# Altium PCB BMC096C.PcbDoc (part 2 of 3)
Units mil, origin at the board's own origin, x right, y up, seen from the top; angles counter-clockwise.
Board outline 5500 x 3200 mil, 4 copper layers (Top Layer, Signal Layer 1, Signal Layer 2, Bottom Layer), stack 61.6 mil thick; 174 components, 74 nets, 402 pads, 1110 vias.
Unrouted connection lines stored in the file: 741.
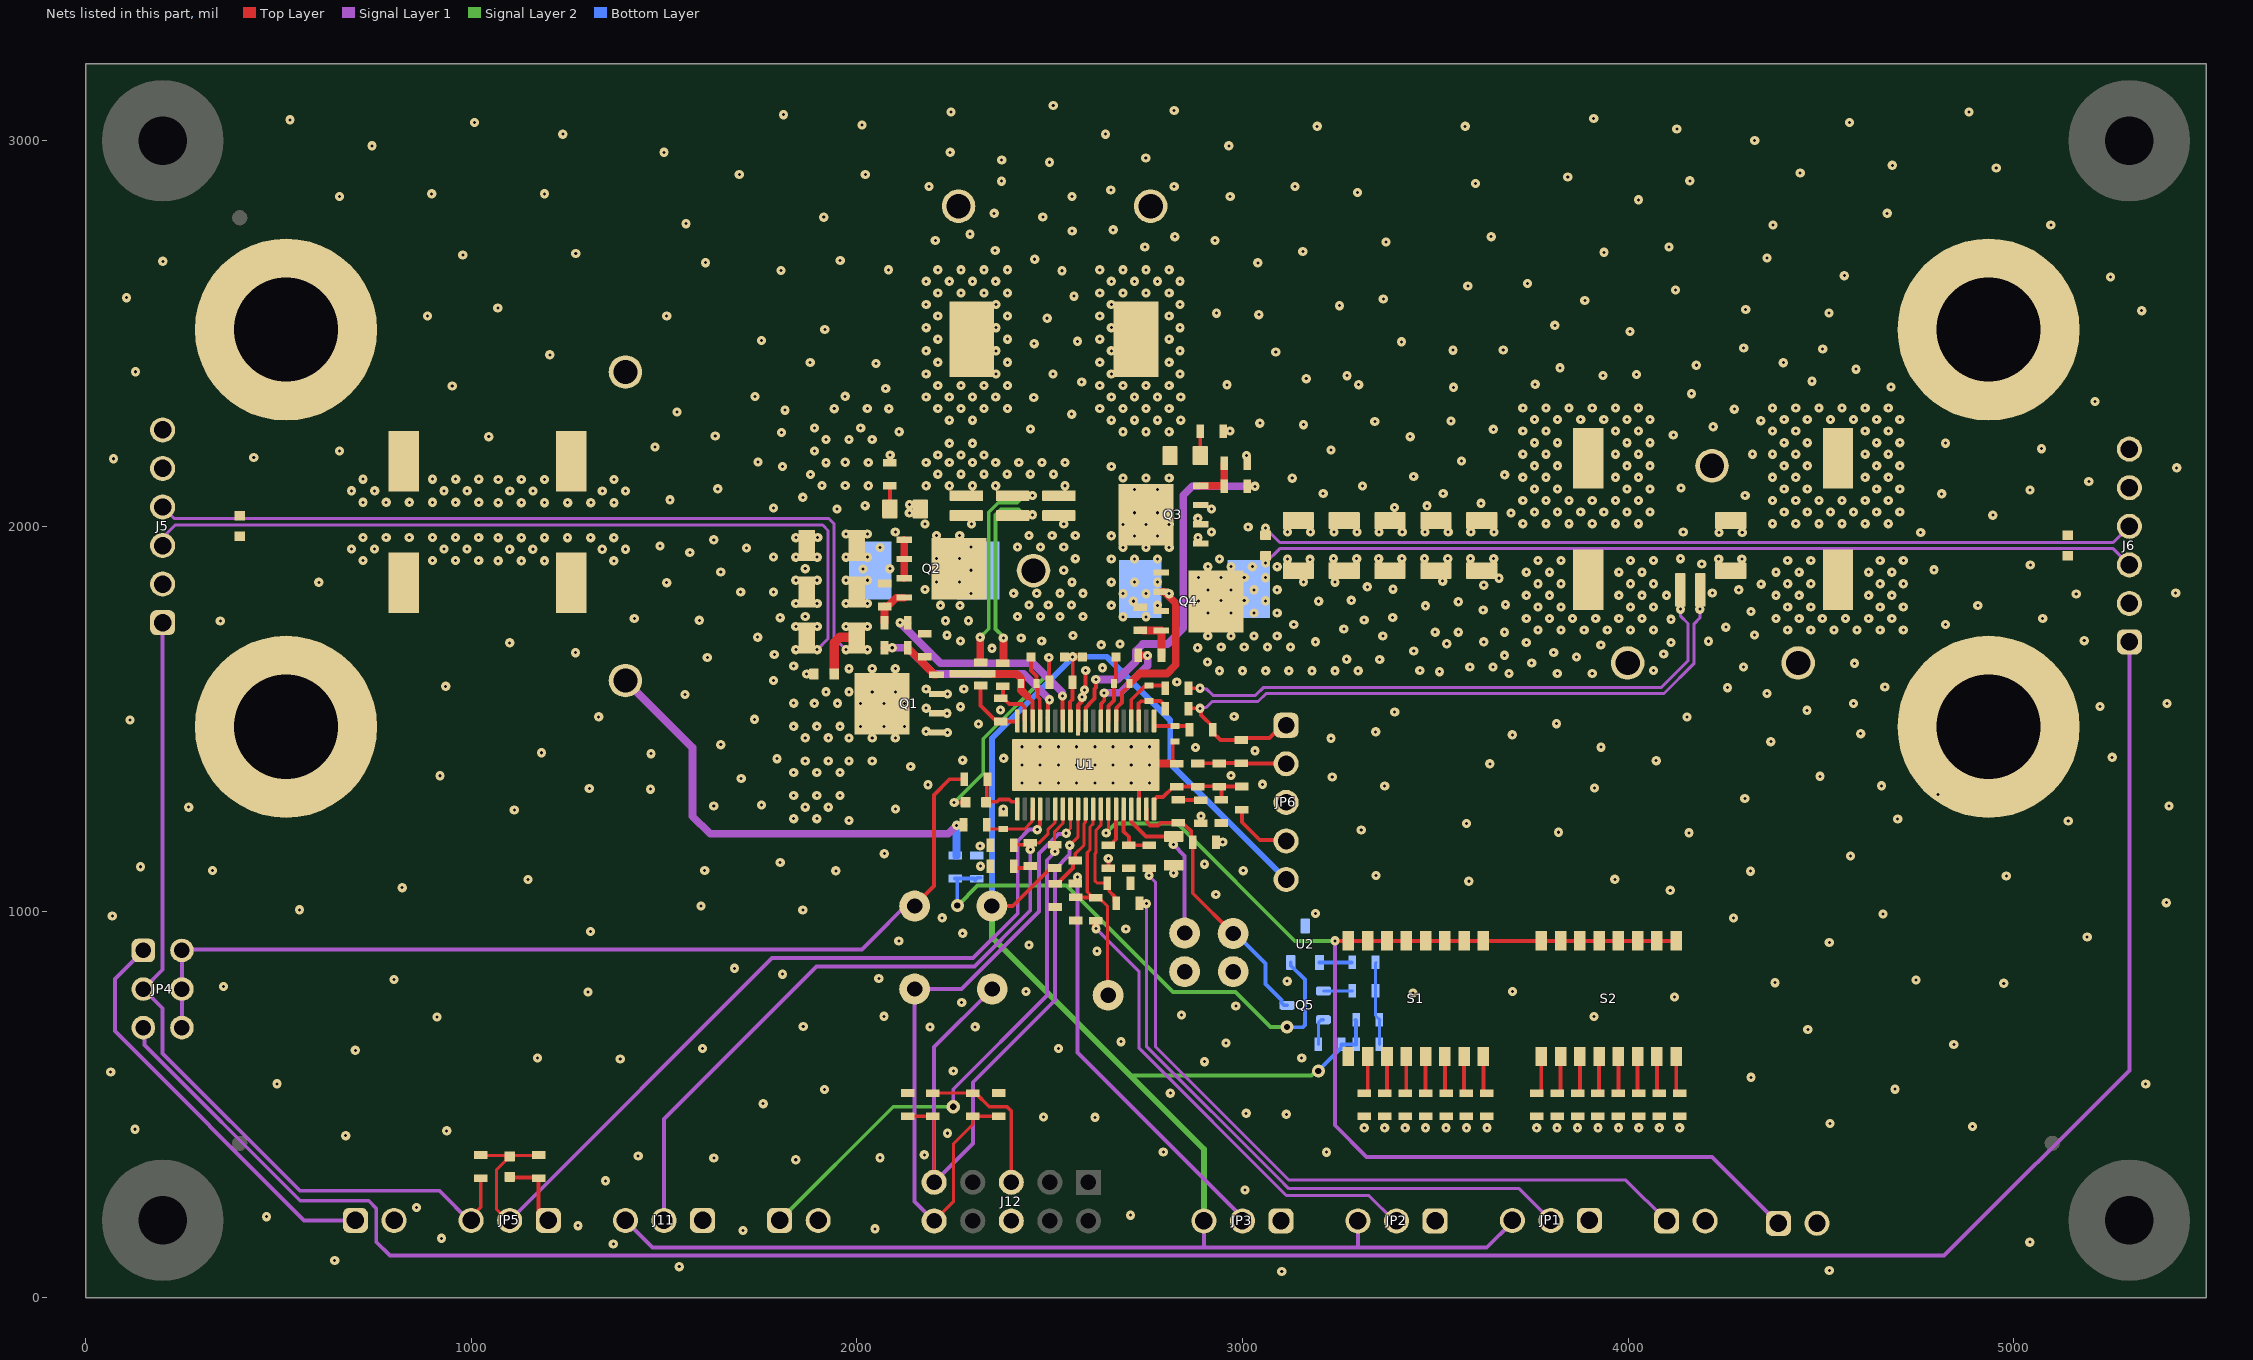
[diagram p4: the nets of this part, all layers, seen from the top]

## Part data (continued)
S1 S2: library part CMP-0002229-1, "Switch, SPST, 8 Pos, 25mA, 24VDC, SMD", CurrentRating_mA=25A, Manufacturer="CTS Electrocomponents", Supplier Part Number 1=CT2188LPST-ND
SH-JP1 SH-JP2 SH-JP3 SH-JP4 SH-JP5: library part CMP-0078738-1, "Single Operation 2.54mm Pitch Open Top Jumper Socket", Manufacturer=Harwin, Supplier Part Number 1=952-2881-ND
TP1: library part CMP-0055147-2, "Test Point, Multipurpose, Red, TH", Color=Red, Manufacturer="Keystone Electronics", Supplier Part Number 1=36-5010-ND
TP2 TP8: library part CMP-0055150-2, "Test Point, Multipurpose, Orange, TH", Color=Orange, Manufacturer="Keystone Electronics", Supplier Part Number 1=36-5013-ND
TP3 TP4: library part CMP-0055148-2, "Test Point, Multipurpose, Black, TH", Color=Black, Manufacturer="Keystone Electronics", Supplier Part Number 1=36-5011-ND
TP5 TP6: library part CMP-0055149-2, "Test Point, Multipurpose, White, TH", Color=White, Manufacturer="Keystone Electronics", Supplier Part Number 1=36-5012-ND
TP7: library part CMP-0055159-2, "Test Point, Multipurpose, Grey, TH", Color=Grey, Manufacturer="Keystone Electronics", Supplier Part Number 1=36-5128-ND
TP9 TP10 TP11 TP12 TP13 TP14 TP15: library part CMP-0055141-2, "Test Point, Miniature, Yellow, TH", Color=Yellow, Manufacturer="Keystone Electronics", Supplier Part Number 1=36-5004-ND
TP16 TP17: library part CMP-0055138-2, "Test Point, Miniature, Black, TH", Color=Black, Manufacturer="Keystone Electronics", Supplier Part Number 1=36-5001-ND
U1: library part CMP-0094661-2, "Wide VIN Bidirectional 4 Switch Buck-Boost Controller", Manufacturer="Texas Instruments", Max Supply Voltage=78V, Min Supply Voltage=2.8V, Nominal Supply Current=25uA, Operating Temperature Range="-40°C to +125°C", Output Voltage=3.3-78V, Switching Frequency=100-2000kHz
U2: library part CMP-0032992-1, "Low-Voltage Adjustable Precision Shunt Regulator, 129 ppm / degC, 80 mA, 0 to 70 degC, 3-pin SOT-23 (DBZ), Green (RoHS & no Sb/Br)", Manufacturer="Texas Instruments", Rating=Catalog, Temp Coeff(Max)(ppm/ degree C)=129
ZZ2: library part CMP-0077236-1
ZZ3: library part CMP-0077237-1
ZZ4: library part CMP-0077238-1

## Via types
v1: diameter 24, hole 7.87, Top Layer to Bottom Layer, tented both sides, 1082 vias
v2: diameter 19.68, hole 7.87, Top Layer to Bottom Layer, 24 vias
v3: diameter 34, hole 16, Top Layer to Bottom Layer, tented both sides, 4 vias

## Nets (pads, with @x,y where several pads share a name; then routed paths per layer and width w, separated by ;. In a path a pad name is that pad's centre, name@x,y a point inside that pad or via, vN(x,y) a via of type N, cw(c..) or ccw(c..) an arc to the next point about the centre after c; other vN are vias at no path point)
AGND: C18.2 C19.2 C20.1 C26.1 C27.2 C28.2 C33.1 C34.2 C35.2 C36.2 C37.2 J7.2 J8.2 J9.2 J10.2 J11.1 J12.6 JP1.1 JP2.1 JP3.1 JP5.1 JP6.3 NT1.2 R2.1 R15.1 R18.1 R20.1 R21.1 R24.1 R25.1 R26.1 R27.1 R28.1 R29.1 R30.1 R31.1 R32.1 R33.1 R34.1 R35.1 R36.1 R37.1 R38.1 R51.1 R52.1 R54.1 S1.1 TP16.1 TP17.1 U1.17 U1.39 U2.3 | length 504.7
  Top Layer w10: C28.2@1100,312.92 1101.71,311.21 1173.29,311.21 R15.1@1175,309.5 1175,225.49 1200,200.49 JP5.1@1200,194.41 ; C26.1@2380,1255 v1(2380,1267) ; U1.39@2574,1432.24 v2(2570,1428.24) 2593.62,1404.62 U1.39@2593.62,1381 ; R20.1@2652,1113 2652.42,1113.42 v1(2652.42,1138.44) ; U1.39@2711,1333 2717.49,1333 2731.42,1319.07 U1.17@2731.42,1266.83 ; v2(2758.98,1428.24) U1.39@2760.36,1429.63 ; C27.2@2819.22,1442 2819.22,1386.78 R2.1@2820,1386
  Top Layer w20: U1.39@2759,1383 2761,1385 R2.1@2824,1385
  other v1: 3102.03,67.61 4522.07,70.11 1539.59,80 646.16,96.1 1368.62,138.97 5042.03,143.61 922.99,153.64 1704.82,173.95 2047.48,178.16 1277.24,186.36 469.03,209.61 2710.03,213.43 858.03,233.61 3006.74,278.87 1348.32,302.56 1841.75,357.28 1629.17,362.08 2060.46,362.47 1433.18,366.86 2175.13,370.21 2795.01,377.44 3218.03,377.05 674.65,419.78 2235,426 936.53,432.3 128.58,436.43 3316,440 3369,440 3422,440 3475,440 3528,440 3581,440 3634,440 3763,440 3816,440 3869,440 3922,440 3975,440 4028,440 4081,440 4134,440 4893.06,443.58 4523.75,451.53 2617.52,467.27 2484.4,468.4 3113.92,475.17 3009.86,477.65 1757.39,502.65 2813,530 1916.52,539.73 4692.23,540.42 496.54,554.14 5342.25,553.84 4318.82,571.14 65.22,584.61 2250.33,587.61 2901.82,611.68 1386.67,618.45 1172.1,620.87 3153.64,621 699.61,641.01 1600,645.57 2523.35,645.57 4844.8,656.15 2957.56,660.24 2685.21,663.58 4466.2,694.96 2190.13,701.7 2307.16,702.1 1861.22,702.54 911.17,727.19 2070.85,729.14 3911.54,729.01 2842.03,732.4 2983.05,756.09 2271.94,764.79 4120.45,779.64 3442.22,789.93 1303.19,792.19 2438.67,793.42 3700.61,793.75 357.77,806.86 4974.29,814.75 4381.03,816.61 3116.18,820.39 4747.03,823.61 800,824.87 2057.03,827.61 1807.34,838.51 1683.03,853.61 2623.16,898.24 2446.76,914.12 4521.89,920.8 2108.95,924.26 5190.55,934.87 2274.51,944.55 1309.7,948.98 2697.62,955.78 4273.26,984.26 2221.52,984.54 69.5,989.45 4661.34,994.85 3189.74,995.55 554.7,1005.43 1860,1004.63 1596.23,1015.45 5396,1024 2931.15,1044.9 4109.45,1055.99 821.05,1062.72 3587.09,1079.53 1147.19,1083.99 3965.7,1084.39 4981,1093 3346.33,1094.54 2821.83,1100.37 1945.74,1106.45 4317.87,1105.61 3002.23,1106.95 329.47,1107.62 1605.68,1107.62 142.76,1117.08 2321,1118.57 2901.82,1123.67 1801.34,1128.01 4577,1145 2071.36,1151.13 2320,1170.68 2949,1181.04 4158.2,1205.15 3819.87,1206.61 3308.18,1212.16 3581,1229 1980,1236.89 2892.5,1248.92 2100.12,1266.61 4302.99,1293.92 3913,1321.57 3369,1326.35 2184.71,1329.78 3052.03,1330.83 3232.99,1350.09 2970.33,1353.69 2139.8,1377.05 3641.54,1384.08 4073.07,1392.14 2274.51,1393.59 2380.87,1398.32 3032.77,1417.68 2878.05,1426.17 3929.74,1427.07 3229.76,1450.09 3699.82,1459.08 3345.73,1466.88 2315.62,1487.13 3814.78,1488.19 4153.11,1505.65 2978.71,1507 3394.81,1518.29
  other v2: 2428.27,1333.76 2475.51,1333.76 2522.76,1333.76 2570,1333.76 2617.24,1333.76 2664.49,1333.76 2711.73,1333.76 2758.98,1333.76 2428.27,1381 2475.51,1381 2522.76,1381 2570,1381 2617.24,1381 2664.49,1381 2711.73,1381 2758.98,1381 2428.27,1428.24 2475.51,1428.24 2522.76,1428.24 2617.24,1428.24 2664.49,1428.24 2711.73,1428.24
BIAS: C29.2 R44.1 U1.1 | length 164.4
  Top Layer w10: C29.2@2335.53,1284.59 C29.2@2336.43,1285.5 ; R44.1@2338.78,1344.16 2337.15,1342.54 2337.15,1286.22 C29.2@2336.43,1285.5 ; U1.1@2416.46,1266.83 2416.46,1284.59 2415.55,1285.5 2401.41,1285.5 2395.03,1291.87 2369.7,1291.87 2363.32,1285.5 C29.2@2336.43,1285.5
CFG: J8.1 S1.9 S1.10 S1.11 S1.12 S1.13 S1.14 S1.15 S1.16 S2.9 S2.10 S2.11 S2.12 S2.13 S2.14 S2.15 S2.16 U1.13 | length 3412.1
  Top Layer w8: v1@2647,1205 2647,1209.23 2652.68,1214.9 U1.13@2652.68,1266.83
  Top Layer w10: v1(3240,925) S1.16@3275,925 S1.15@3325,925 S1.14@3375,925 S1.13@3425,925 S1.12@3475,925 S1.11@3525,925 S1.10@3575,925 S1.9@3625,925 S2.16@3775,925 S2.15@3825,925 S2.14@3875,925 S2.13@3925,925 S2.12@3975,925 S2.11@4025,925 S2.10@4075,925 S2.9@4125,925
  Signal Layer 1 w10: v1(3240,925) 3240,446.68 3322.09,364.59 4217.86,364.59 J8.1@4390,192.46
  Signal Layer 2 w10: v1(2646.64,1204.44) 2671.04,1228.83 2831.99,1228.83 3135.82,925 v1(3240,925)
COMP: C19.1 Q5.3 R19.2 TP13.1 U1.18 | length 726.6
  Top Layer w10: U1.18@2751.1,1266.83 2752.01,1265.92 2752.01,1233.11 2760.69,1224.43 2780.88,1224.43 2787.63,1231.17 R19.2@2833.28,1231.17 2838.28,1226.17 2849.53,1226.17 2866.25,1209.45 2866.25,1186.04 C19.1@2871.25,1181.04 2871.25,1048.54 TP13.1@2975.84,943.95
  Bottom Layer w10: TP13.1@2975.84,943.95 2982.03,943.95 3059.98,866 3059.98,813.45 3101.52,771.91 3101.52,764.53 3108.26,757.78 Q5.3@3115.65,757.78
CSA/SW1: C21.2 R11.1 U1.37 | length 138
  Top Layer w10: C21.2@2373,1553.84 C21.2@2379,1553.84 ; R11.1@2378,1585 2379,1584 C21.2@2379,1553.84 ; U1.37@2436.14,1497.17 2435.24,1498.08 2435.24,1531.9 2428.24,1538.89 2395.45,1538.89 2380.5,1553.84 C21.2@2379,1553.84
CSB: C21.1 R12.1 U1.38 | length 169.7
  Top Layer w10: R12.1@2321,1587 2321,1534.9 2357.07,1498.84 2368,1498.84 C21.1@2373,1493.84 ; C21.1@2369.43,1494 2415.55,1494 2416,1493.55 U1.38@2416,1493 ; U1.38@2416.46,1505.17 U1.38@2417.36,1506.08
DTRK: C36.1 R50.2 U1.10 | length 234.3
  Top Layer w8: R50.2@2566.5,1133.4 R50.2@2566.5,1133.4 2566.45,1150.71 2589,1173.26 2589,1229 2592.59,1232.59 2592.59,1265.8 U1.10@2593.62,1266.83
  Top Layer w10: C36.1@2514.08,1072.87 2521.58,1072.87 2526.58,1077.87 2526.58,1080.09 2560.75,1114.26 2560.75,1128.4 2564,1128.4 R50.2@2569,1133.4
EN/UVLO: C28.1 JP5.2 R14.1 R15.2 U1.4 | length 2303.2
  Top Layer w8: R14.1@1025,369.5 1026.71,367.78 C28.1@1090.22,367.78 ; JP5.2@1100,194.41 1066.01,228.4 1066.01,332.08 1090.22,356.29 C28.1@1090.22,367.78 ; R15.2@1175,369.5 1173.29,367.78 C28.1@1090.22,367.78
  Top Layer w10: v1(2467.97,1213.33) 2467.97,1217.11 2475.51,1224.65 U1.4@2475.51,1266.83
  Signal Layer 1 w10: JP5.2@1100,200 1780.46,880.46 2301.74,880.46 2417.53,996.24 2417.53,1183.93 2446.92,1213.33 v1(2467.97,1213.33)
FB: C16.2 C37.1 R1.2 R2.2 R46.1 U1.19 | length 286.4
  Top Layer w10: U1.19@2770.79,1266.83 2770.79,1290.45 2778.4,1298.06 2794.47,1298.06 2820.79,1324.39 R2.2@2830.06,1324.39 ; R2.2@2830.06,1324.2 R2.2@2830.06,1324.39 ; R2.2@2832.54,1324.39 R2.2@2830.06,1324.39 ; R1.2@2868,1325 2830.06,1325 R2.2@2830.06,1324.39 ; R1.2@2879,1325 2879.67,1325.67 2932.5,1325.67 C16.2@2933.18,1326.35 ; C37.1@2945.63,1290.58 2945.63,1319.92 2940.63,1324.92 2997.36,1324.92 R46.1@2997.63,1325.19
FLT: J9.1 R16.2 U1.7 | length 1463.3
  Top Layer w8: R16.2@2513,1174 2513,1208 2534.57,1229.57 U1.7@2534.57,1266.83 U1.7@2533.57,1265.83
  Top Layer w20: v1(2513.69,1156.34) R16.2@2513.69,1173.31
  Signal Layer 1 w10: v3(2250.3,494.62) 2250.3,540.1 2493.1,782.9 2493.1,1134.05 2513.69,1154.65 v1(2513.69,1156.34)
  Signal Layer 2 w10: J9.1@1800,200 2094.62,494.62 v3(2250.3,494.62)
GND: C1.2 C2.1 C3.1 C4.1 C5.2 C6.2 C7.2 C8.1 C9.1 C10.1 C11.1 C12.1 C13.2 C14.1 C15.2 C17.1 C29.1 C31.2 C32.2 C40.1 C41.1 D2.2 J3.1 J4.1 J5.4 J5.5 J5.6 J6.4 J6.5 J6.6 NT1.1 Q2.1 Q2.2 Q2.3 Q3.1 Q3.2 Q3.3 R13.1 R39.1 TP3.1 TP4.1 U1.30 | length 5375.2
  Top Layer w10: v1(2252.63,1283.65) 2253.1,1284.12 2281.91,1284.12 C29.1@2282.38,1284.59 ; v1(2498,1660) 2498.78,1659.22 2498.78,1596.94 C17.1@2499.57,1596.16 ; U1.30@2573.94,1495.17 2574,1495.11 NT1.1@2574,1462 ; v1@2585.69,1558 2585.69,1561.79 2591.85,1567.94 2591.85,1573.24 2594.53,1575.92 2593.35,1577.1 2593.35,1625.69 v1(2593.62,1625.97)
  Top Layer w11.81: U1.30@2573.94,1495.17 2573.94,1536.4 2583.36,1545.83 2583.36,1555.67 v1@2585.69,1558
  Top Layer w20: Q2.3@2122.87,1865 Q2.2@2122.87,1915 Q2.1@2122.87,1965
  Top Layer w25: C1.2@1941.57,1616.93 1941.57,1697.86 1956.22,1712.5 1997.46,1712.5 C2.1@1999.96,1710 1994.96,1705 C2.1@1990,1705
  Signal Layer 1 w8: J5.4@200,2050 229.3,2020.7 1926.6,2020.7 1941.24,2006.06 1941.24,1995.78 1941.36,1995.65 1941.36,1710.56 v1(1971.92,1680) ; v1(3060,1995) 3097.04,1957.96 5257.96,1957.96 J6.4@5300,2000
  Signal Layer 2 w10: v1(2252.63,1283.65) 2327.87,1358.9 2327.87,1449.03 2498,1619.16 v1(2498,1660)
  other v1: 2373,1523.77 2584.53,1556.83 2590.51,1575.29 2830.06,1596.07 2637.23,1633.01 2027.35,1680 2350.33,1683.5 2633.94,1692.5 2682.47,1694.49 2479.47,1702.3 2426.3,1710 2560.75,1716.74 1971.92,1740 2027.35,1740 1971.92,1800 2027.35,1800 1971.92,1860 2027.35,1860 2016.38,1889.19 2085.69,1890 1971.92,1920 2027.35,1920 2060.27,1944.7 2885.05,1970.44 1971.92,1980 2027.35,1980 4236.18,1984.08 4296.18,1984.08 4759,1984 2100.08,1985.11 2920.08,1985.11 3116.89,1985.08 3176.89,1985.08 3237.46,1985.08 3297.46,1985.08 3354.46,1985.08 3414.46,1985.08 3473.46,1985.08 3533.46,1985.08 3592.46,1985.08 3652.46,1985.08 4143.18,1985.08 3014.84,1997.93 3727.2,2006.84 3787.2,2006.84 3847.2,2006.84 3907.2,2006.84 3967.2,2006.84 4027.2,2006.84 4374.92,2006.84 4434.92,2006.84 4494.92,2006.84 4554.92,2006.84 4614.92,2006.84 4674.92,2006.84 2884.41,2020.62 4945.89,2028.67 3696.22,2034.14 3757.2,2036.84 3817.2,2036.84 3877.2,2036.84 3937.2,2036.84 3997.2,2036.84 4057.2,2036.84 4404.92,2036.84 4464.92,2036.84 4524.92,2036.84 4584.92,2036.84 4644.92,2036.84 4704.92,2036.84 1948.65,2045.08 2920.08,2045.11 1784,2047.63 3394.43,2048.9 3478.93,2052.92 2021.8,2053.56 3618.42,2059.63 1070.22,2061.24 1130.22,2061.24 1190.22,2061.24 1250.22,2061.24 1310.22,2061.24 1370.22,2061.24 719.73,2062.01 779.73,2062.01 839.73,2062.01 899.73,2062.01 959.73,2062.01 1019.73,2062.01 3727.2,2066.84 3787.2,2066.84 3847.2,2066.84 3907.2,2066.84 3967.2,2066.84 4027.2,2066.84 4374.92,2066.84 4434.92,2066.84 4494.92,2066.84 4554.92,2066.84 4614.92,2066.84 4674.92,2066.84 1515.54,2068.62 1860.08,2075 4303.82,2079.74 4813.4,2084.24 3209.33,2085.11 3520.51,2085.11 1100.22,2091.24 1160.22,2091.24 1340.22,2091.24 1400.22,2091.24 689.73,2092.01 749.73,2092.01 929.73,2092.01 989.73,2092.01 5042.36,2094.34 1639.46,2097.01 3757.2,2096.84 3817.2,2096.84 3997.2,2096.84 4057.2,2096.84 4404.92,2096.84 4464.92,2096.84 4644.92,2096.84 4704.92,2096.84 4137.18,2099.51 3311.63,2104.44 2030,2105.11 1910.08,2106 1970.08,2106 5194.99,2115.84 1070.22,2121.24 1130.22,2121.24 1190.22,2121.24 1370.22,2121.24 719.73,2122.01 899.73,2122.01 959.73,2122.01 1019.73,2122.01 3129.23,2124.65 3727.2,2126.84 3787.2,2126.84 3967.2,2126.84 4027.2,2126.84 4374.92,2126.84 4434.92,2126.84 4614.92,2126.84 4674.92,2126.84 3444.06,2129.37 3680.12,2133.4 1880,2134 5422.83,2151.58 1807.31,2155.11 3757.2,2156.84 3817.2,2156.84 3997.2,2156.84 4057.2,2156.84 4404.92,2156.84 4464.92,2156.84 4644.92,2156.84 4704.92,2156.84 1920.08,2165 2030,2165.11 1970.08,2166 1744.02,2166.72 3567.96,2169.3 72.58,2175.15 436.22,2178.52 3010.38,2183.02 2086.49,2185.1 3727.2,2186.84 3787.2,2186.84 3967.2,2186.84 4027.2,2186.84 4322.6,2187.05 4374.92,2186.84 4434.92,2186.84 4614.92,2186.84 4674.92,2186.84 658.45,2195.36 1890.08,2195 3229.76,2197.7 5072.48,2201.16 1476.64,2205.46 4823.5,2215.56 3757.2,2216.84 3817.2,2216.84 3997.2,2216.84 4057.2,2216.84 4404.92,2216.84 4464.92,2216.84 4644.92,2216.84 4704.92,2216.84 1920.08,2225 1980,2225 2040,2225 1045.66,2232.39 3434.93,2232.39 1633.01,2233.84 4117.38,2236.67 1805.06,2243.14 2109.98,2245.11 2967.86,2246.84 3727.2,2246.84 3787.2,2246.84 3967.2,2246.84 4027.2,2246.84 4374.92,2246.84 4434.92,2246.84 4614.92,2246.84 4674.92,2246.84 3650.61,2251.43 2450.18,2252.07 1890.08,2255 2010,2255 4220.66,2258.14 3158.36,2263.5 3045.17,2267.4 3343.46,2271.55 3540.63,2272.89 4344.31,2273.82 3757.2,2276.84 3817.2,2276.84 3877.2,2276.84 3937.2,2276.84 3997.2,2276.84 4057.2,2276.84 4404.92,2276.84 4464.92,2276.84 4524.92,2276.84 4584.92,2276.84 4644.92,2276.84 4704.92,2276.84 2557.18,2290.64 1533.88,2296.37 1813.72,2300.96 4275.65,2303.74 1941.57,2305 2027.35,2305.11 2083.08,2305 3727.2,2306.84 3787.2,2306.84 3847.2,2306.84 3907.2,2306.84 3967.2,2306.84 4027.2,2306.84 4374.92,2306.84 4434.92,2306.84 4494.92,2306.84 4554.92,2306.84 4614.92,2306.84 4674.92,2306.84 5210.71,2323.3 2458.89,2334.18 1735.91,2336.77 1969.91,2337.11 4164.32,2343.98 2075,2357 3547.38,2360.34 4682.06,2361.41 951,2364 2959.98,2366.8 3301.59,2367.08 3759.26,2368.12 2583.31,2374 4476.84,2376.17 3165.56,2382.8 3271.28,2390.64 3934.97,2390.92 4022.15,2393.6 2508.66,2395.15 129.82,2400.75 4591.17,2407.48 3823.48,2410.85 4177.02,2417.58 2049.95,2422.3 4402.62,2424.32 1879.04,2424.73 1203.91,2444.52 3086.48,2451.99 3545.99,2456.65 3676.39,2457.16 4504.83,2459.83 4299.79,2462.01 2460.14,2473.53 3412.7,2478.19 2572.11,2479.75 1752.74,2481.55 4005.3,2505.12 1916.99,2510.08 3810.23,2521.03 2493.73,2539.47 887.05,2545.53 1506.95,2545.53 3042.59,2548.8 2932.87,2552.68 4521.1,2553.22 5331.92,2559 4304.97,2562.36 1069.23,2565.73 3251.71,2572.04 3888.02,2585.41 3365.56,2589.3 106.25,2592.67 2563.4,2596.7 4123.34,2613 3584.42,2622.97 3739.31,2629.71 5251.11,2646.54 4560.87,2649.91 1803.25,2663.38 2532.3,2662.64 2082.22,2665.11 3040.01,2683.05 1607.96,2683.58 200.53,2686.95 1957.01,2689.5 2461.38,2692.5 4360.15,2695.39 978.32,2703.78 1271.25,2707.15 3937.96,2710.51 3156.8,2712.77 4106.31,2723.98 3372.3,2737.45 2929,2741.14 3645.03,2750.92 2558.42,2765.9 4375.68,2781.22 5096.23,2781.22 1557.45,2784.59 1914.36,2801.43 2482.53,2801.98 4671.98,2811.53 4026.89,2846.67 658.45,2855.3 2558.1,2855.3 2968.25,2855.3 897.51,2862.03 1190.44,2862.03 3298.22,2865.4 3136.6,2881.12 3604.62,2888.97 4160.19,2895.7 3843.68,2905.8 1695.5,2912.54 2022.11,2912.54 4446.39,2915.91 4954.81,2929.37 4685.45,2936.11 2500,2944 2375.65,2949.58 2749.39,2955.2 1500.21,2969.78 2242.28,2969.61 742.62,2986.61 2964.88,2986.61 4328.54,3000.08 1237.58,3016.92 2645.01,3016.92 4126.52,3030.39 3193.84,3037.12 3577.69,3037.12 2013.8,3040.61 1008.62,3047.22 4574.34,3047.22 530.5,3053.95 3911.03,3057.32 1809.98,3067.42 2244.33,3074.16 4884.1,3074.16 2823.15,3078.04 2509.48,3090.95
HB1: C24.2 D3.1 U1.35 | length 174.7
  Top Layer w10: D3.1@2451.69,1660 2451.69,1625.97 2465.94,1611.72 2465.94,1592 2468.48,1589.46 2468.48,1558.23 2474.61,1552.11 2474.61,1523.3 2474.61,1496.08 U1.35@2475.51,1495.17
HB2: C25.2 D4.1 U1.26 | length 178
  Top Layer w10: U1.26@2652.68,1495.17 2653.11,1495.61 2653.11,1534.01 2667.04,1547.94 C25.2@2667.04,1592 2667.04,1596.5 2672.31,1601.76 D4.1@2672.31,1665
HO1: R7.1 U1.34 | length 522.8
  Top Layer w10: U1.34@2495,1503 2495.49,1503.49 v1@2495.49,1541.7
  Top Layer w20: R7.1@2072,1685 v1(2092,1685)
  Signal Layer 1 w20: v1(2092,1685) 2131.23,1685 2199.11,1617.13 2432.87,1617.13 v1(2500,1550)
HO1_G: C38.1 Q1.4 R7.2 | length 109
  Top Layer w20: R7.2@2132,1685 2132,1679.32 2137.68,1679.32 2197.44,1619.56 2197.44,1616.93 2199.37,1615 Q1.4@2207.13,1615
HO2: R8.1 U1.27 | length 267.9
  Top Layer w10: U1.27@2632.99,1495.17 2632.99,1539.17 2641.61,1547.79 v1(2641.61,1567.94)
  Top Layer w20: R8.1@2730,1664.81 v1@2753.98,1664.81
  Signal Layer 1 w20: v1(2641.61,1567.94) 2682.99,1567.94 2754.18,1639.13 v1(2754.18,1664.61)
HO2_G: C39.2 Q4.4 R8.2 | length 118.5
  Top Layer w20: C39.2@2735.67,1730.07 2743.17,1730.07 2743.25,1730 Q4.4@2789.57,1730 ; R8.2@2790,1665 Q4.4@2790,1729.57
IMONOUT: C33.2 J11.2 R17.2 U1.6 | length 1769.3
  Top Layer w8: R17.2@2450,1174 2458.5,1174 2463.5,1179 2473.47,1179 2495.49,1201.02 2495.49,1212.94 2514.5,1231.95 2514.5,1266.44 U1.6@2514.88,1266.83
  Top Layer w10: C33.2@2406.93,1173 2407.93,1174 R17.2@2450,1174
  Signal Layer 1 w10: J11.2@1500,200 1500,462.73 1895.61,858.34 2304.9,858.34 2450,1003.44 v1(2450,1162.04)
ISNSN: C30.1 R43.1 U1.22 | length 129.2
  Top Layer w10: U1.22@2731.42,1495.17 2731,1495.59 2731,1540.35 2736.86,1546.21 2757.21,1546.21 C30.1@2758,1547 2787.5,1547 2801,1533.5 R43.1@2801,1528
ISNSP: C30.2 R42.1 U1.23 | length 156.4
  Top Layer w10: U1.23@2711.73,1495.17 2711.73,1550.14 2746.09,1584.5 2753.5,1584.5 C30.2@2755.93,1586.93 ; C30.2@2758,1587 R42.1@2800,1587
LO1: R9.2 U1.32 | length 577.3
  Top Layer w10: v1@2533.78,1549.22 2533.78,1498.22 U1.32@2534.57,1497.43
  Top Layer w20: v1(2112,1750) R9.2@2132,1750
  Signal Layer 1 w10: v1@2532.4,1560.63 v1(2533.17,1559.87)
  Signal Layer 1 w20: v1(2112,1750) 2217,1645 2457,1645 2532.4,1569.6 v1@2532.4,1560.63
LO1_G: C40.2 Q2.4 R9.1 | length 102.2
  Top Layer w20: R9.1@2072,1750 2072,1775.74 C40.2@2072,1791.71 2079.5,1791.71 2102.79,1815 Q2.4@2122.87,1815
LO2: R10.2 U1.29 | length 975.9
  Top Layer w10: U1.29@2593.62,1495.17 2594.53,1496.08 2594.53,1530.44 2602.14,1538.05 2602.14,1538.88 2616.74,1553.47 2616.74,1578.25 2620.43,1581.94 v1@2620.43,1601.96
  Top Layer w20: R10.2@3012.74,2103.47 v1(3032.74,2103.47)
  Signal Layer 1 w20: v1(2619.82,1602.57) 2676.19,1602.57 2724.3,1650.68 2724.3,1676.99 2741.8,1694.49 2805.7,1694.49 2846.57,1735.36 2846.57,2080.47 2869.57,2103.47 v1(3032.74,2103.47)
LO2_G: C41.2 Q3.4 R10.1 | length 120.5
  Top Layer w20: Q3.4@2892.13,2105 R10.1@2952.74,2105 ; R10.1@2952.74,2103.47 R10.1@2952.74,2105 ; C41.2@2952.82,2163.32 2952.82,2155.82 2952.74,2155.73 R10.1@2952.74,2105
MODE: C34.1 R47.2 U1.12 | length 289.5
  Top Layer w8: U1.12@2632.99,1266.83 2632.99,1224.55 2620.75,1212.31 2620.75,1154.26 2618.22,1151.73 2618.22,1079.53 2622.91,1074.85 2649.48,1074.85 C34.1@2649.54,1074.91
  Top Layer w10: C34.1@2649.54,1074.91 2654.54,1069.91 2654.54,1053.46 2668.12,1039.88 2668.12,1026.91 R47.2@2673.12,1021.91
NetC7_1: C7.1 C8.2 C9.2 C10.2 C11.2 C12.2 C13.1 D1.1 J6.3 Q4.5 R6.1 R42.2 TP8.1 | length 3755
  Top Layer w10: R42.2@2860,1580 v1(2890,1580)
  Signal Layer 1 w8: v1(2890,1580) 2891.43,1578.57 2906.51,1578.57 2923.57,1561.52 3034.04,1561.52 3054.94,1582.42 4086.73,1582.42 4155.65,1651.33 4155.65,1747.79 4136.34,1767.1 v1(4136.29,1785) v1(4136.29,1785) ; v1(3060,1905) 3097.08,1942.08 5257.92,1942.08 J6.3@5300,1900
  other v1: 3691.09,1618.04 3816.71,1618.04 3907.2,1618.04 3511.2,1622.87 2940.3,1625.19 3000.3,1625.19 3060.3,1625.19 3120.3,1625.19 3180.3,1625.19 3240.3,1625.19 3300.3,1625.19 3460,1625.97 4066.22,1625.97 3589.86,1635.33 3649.86,1635.33 3750.04,1645.57 2909.5,1648 3270.3,1655.19 3355.85,1654.59 3866.12,1661.05 3679.86,1665.33 4092.5,1668.71 3807.18,1672.94 3444.36,1676.33 2884.15,1685 2944.82,1686.97 3004.82,1686.97 3064.82,1686.97 3124.82,1686.97 3929.38,1692.41 3529.86,1695.33 3736.22,1698.71 4111.15,1698.71 3189.71,1700.4 3625.89,1700.4 2910.3,1715.19 2970.3,1715.19 3030.3,1715.19 3090.3,1715.19 3364.07,1715.19 3499.86,1725.33 3559.86,1725.33 3679.86,1725.33 3766.22,1730.96 3826.22,1730.96 3886.22,1730.96 3946.22,1730.96 4006.22,1730.96 4066.22,1730.96 3263.07,1733.39 3133.12,1745.53 3315.68,1756.72 4111.15,1758.71 3736.22,1760.96 3796.22,1760.96 3856.22,1760.96 3916.22,1760.96 3976.22,1760.96 4036.22,1760.96 3389.62,1763.67 2910.3,1775.19 2970.3,1775.19 3030.3,1775.19 3090.3,1775.19 3624.41,1782.71 3766.22,1790.96 3826.22,1790.96 4006.22,1790.96 4066.22,1790.96 3475,1793.86 3682.27,1796.77 3559.86,1804.26 3197.86,1805.6 2885.77,1806.51 2944.82,1806.97 3004.82,1806.97 3060.03,1806.58 3282.36,1808.02 3736.22,1820.96 3796.22,1820.96 3976.22,1820.96 4036.22,1820.96 4100.04,1820.96 2910.3,1835.19 2970.3,1835.19 3030.3,1835.19 3090.3,1835.19 3390.3,1836.98 3324,1843 3625.89,1847.21 3766.22,1850.96 3826.22,1850.96 4006.22,1850.96 4066.22,1850.96 3240.3,1855.11 3158.36,1856.01 3519.43,1857.66 3665.43,1865.19 2885.77,1866.97 2944.82,1866.97 3004.82,1866.97 3060.03,1866.58 3736.22,1880.96 3796.22,1880.96 3976.22,1880.96 4036.22,1880.96 2910.3,1895.19 2970.3,1895.19 3025.84,1895.19 3090.3,1895.19 3766.22,1910.96 3826.22,1910.96 4006.22,1910.96 4066.22,1910.96 3175.09,1914.22 2940.3,1915.11 3116.92,1914.61 3236.46,1916.08 3296.46,1916.08 3353.46,1916.08 3413.46,1916.08 3472.46,1916.08 3532.46,1916.08 3591.46,1916.08 3651.46,1916.08 4136.29,1916.08
NetC16_1: C16.1 JP6.2 R1.1 R45.1 | length 228.3
  Top Layer w10: R1.1@2879,1385 2879.67,1385.67 2932.5,1385.67 2933.18,1386.35 2933.52,1386 2989.73,1386 R45.1@2990.08,1385.65 ; R45.1@2997.63,1385.53 2998.35,1384.8 3112.72,1384.8 JP6.2@3113.44,1384.08
NetC18_1: C18.1 R19.1 | length 59.8
  Top Layer w10: R19.1@2833.28,1291.17 2834.02,1290.43 2891.76,1290.43 C18.1@2892.5,1289.7
NetC22_1: C22.1 R13.2 | length 60
  Top Layer w10: C22.1@2085.69,2045.08 R13.2@2085.69,2105.11
NetC22_2: C22.2 C38.2 D2.1 NT2.2 Q1.1 Q1.2 Q1.3 Q2.5 R3.1 R4.1 R5.1 R11.2 TP5.1 | length 501.6
  Top Layer w20: R11.2@2378,1645 2380.21,1645 2380.21,1709.79 v1(2380,1710)
  Signal Layer 2 w10: v1(2380,1710) 2380,1713.5 2360.08,1733.42 2360.08,2029 2374.36,2043.28 2419.15,2043.28 2432.64,2029.79 v1(2455.59,2029.79)
  other v1: 2235.26,1465.5 2180.08,1468.3 2233.98,1515 2180.08,1528.3 2268.78,1532.3 2235.26,1565 2180.08,1578.3 2277.69,1578.3 2268.78,1702.3 2233.98,1717.5 2229.97,1755 2289.97,1755 2416.73,1766.01 2476.73,1766.01 2526.73,1766.01 2586.73,1766.01 2217,1795.11 2267.61,1794.73 2446.73,1796.01 2496.73,1796.01 2556.73,1796.01 2296.73,1826.01 2406.73,1826.01 2466.73,1826.01 2526.73,1826.01 2586.73,1826.01 2176.73,1836.01 2558.1,1855.11 2206.73,1856.01 2266.73,1856.01 2296.73,1886.01 2536.73,1886.01 2206.73,1916.01 2266.73,1916.01 2566.73,1916.01 2296.73,1946.01 2416.73,1946.01 2476.73,1946.01 2536.73,1946.01 2206.73,1976.01 2266.73,1976.01 2446.73,1976.01 2506.73,1976.01 2566.73,1976.01 2176.73,2006.01 2297.46,2006.01 2536.73,2006.01 2136.2,2034.24 2136.87,2055.91
NetC23_1: C23.1 R39.2 | length 63.9
  Top Layer w10: R39.2@2890.67,2246.84 2890.67,2183.06 C23.1@2890.73,2183
NetC26_2: C26.2 R40.1 U1.3 | length 166.8
  Top Layer w8: R40.1@2338,1227 2338,1220 2343,1215 2435.47,1215 2453.92,1233.45 2453.92,1264.92 U1.3@2454.92,1265.92
  Top Layer w10: U1.3@2454.92,1265.92 U1.3@2455.83,1266.83
NetC27_1: C27.1 R41.1 U1.20 | length 108
  Top Layer w10: U1.20@2770.79,1495.17 2770.79,1482.91 2771.69,1482 C27.1@2818.17,1482 ; C27.1@2819.22,1482 2863,1482 R41.1@2866,1479
NetC42_2: C42.2 R55.1 R56.2 R57.2 | length 218.7
  Bottom Layer w8: R56.2@3346.5,869 3345,867.5 R57.2@3345,795.19 3345,731.5 3356.5,720 3355,718.5 C42.2@3355,656.26
NetJ10_1: J10.1 R49.2 | length 1982
  Top Layer w8: R49.2@2757.9,1113 R49.2@2758,1112.9
  Top Layer w20: v1(2758,1094.38) R49.2@2758,1112.9
  Signal Layer 1 w8: v1(2758,1094.38) 2758,1093.99 2774.78,1077.22 2774.78,650.22 3100.15,324.85 3100.29,324.85 3120.78,304.36 3994.41,304.36 J10.1@4100,198.77
NetJP1_2: JP1.2 R47.1 | length 1624
  Top Layer w8: R47.1@2733.12,1021.91 R47.1@2733.56,1021.47
  Top Layer w20: R47.1@2733.56,1021.47 v1(2750.9,1021.47)
  Signal Layer 1 w8: v1(2750.9,1021.47) 2750.9,651.65 3093.57,308.98 3093.71,308.98 3120.32,282.37 3717.63,282.37 JP1.2@3800,200
NetJP2_2: JP2.2 R48.1 | length 1229.7
  Top Layer w8: R48.1@2620.15,976.91 R48.1@2620.59,976.47
  Top Layer w20: v1(2620.59,956.47) R48.1@2620.59,976.47
  Signal Layer 1 w8: v1(2620.59,956.47) 2732.25,844.81 2732.25,646.42 3113.89,264.78 3328,264.78 3394.01,198.77 JP2.2@3399.6,198.77
NetJP3_2: JP3.2 R50.1 | length 1089.2
  Top Layer w10: R50.1@2566.5,1073.4 2567.47,1073.4 R50.1@2572.47,1078.4
  Top Layer w20: R50.1@2572.47,1078.4 v1(2572.47,1090.6)
  Signal Layer 1 w10: v1(2572.47,1090.6) 2572.47,635.16 3000.04,207.58 JP3.2@3000.04,198.77
NetJP4_2: JP4.2 JP4.4 JP4.6 R44.2 TP9.1 | length 2559
  Top Layer w10: TP9.1@2152.48,1021.82 2154.25,1021.82 2200,1067.58 2200,1303.05 2241.12,1344.16 R44.2@2278.78,1344.16
  Signal Layer 1 w10: JP4.6@250,700 JP4.4@250,800 JP4.2@250,900 252.57,902.57 2013.22,902.57 TP9.1@2152.48,1041.82
NetL1_1: L1.1 R3.2 R4.2 R5.2 R12.2 TP6.1 | length 530.5
  Top Layer w20: R12.2@2320,1648 v1(2320,1711.94)
  Signal Layer 2 w10: v1(2320,1711.94) 2342.21,1734.15 2342.21,2036.41 2366.96,2061.16 2415.81,2061.16 2436.11,2081.46 2454.29,2081.46 v1(2455.83,2079.92)
  other v1: 2180.08,2105.11 2240.08,2105.11 2300.08,2105.11 2360.08,2105.11 2540.08,2105.11 2210.08,2135.11 2270.08,2135.11 2330.08,2135.11 2390.08,2135.11 2450.08,2135.11 2510.08,2135.11 2180.08,2165.11 2240.08,2165.11 2300.08,2165.11 2360.08,2165.11 2420.08,2165.11 2480.08,2165.11 2540.08,2165.11 2210.08,2185.11 2270.08,2185.11 2330.08,2185.11 2240.08,2215.11 2300.08,2215.11 2240.08,2275.11 2300.08,2275.11 2210.08,2305.11 2270.08,2305.11 2330.08,2305.11 2391.08,2305.11 2180.08,2335.11 2240.08,2335.11 2300.08,2335.11 2360.08,2335.11 2210.08,2365.11 2270.08,2365.11 2330.08,2365.11 2391.08,2365.11 2180.08,2395.11 2361.08,2395.11 2210.08,2425.11 2391.08,2425.11 2180.08,2455.11 2361.08,2455.11 2210.08,2485.11 2391.08,2485.11 2180.08,2515.11 2361.08,2515.11 2210.08,2545.11 2391.08,2545.11 2180.08,2575.11 2361.08,2575.11 2210.08,2605.11 2270.08,2605.11 2330.08,2605.11 2391.08,2605.11 2180.08,2635.11 2240.08,2635.11 2300.08,2635.11 2360.08,2635.11 2210.08,2665.11 2270.08,2665.11 2330.08,2665.11 2391.08,2665.11 2358.98,2715.31 2203.57,2741.14 2293.66,2757.45 2356.34,2811.53 2187.03,2880.94 2375.42,2894.85
NetQ5_1: Q5.1 R57.1 | length 74.9
  Bottom Layer w8: Q5.1@3210.14,795.19 R57.1@3285,795.19
NetQ5_2: Q5.2 R58.2 | length 72.9
  Bottom Layer w8: R58.2@3196.87,656.26 3196.87,712.72 3204.54,720.38 Q5.2@3210.14,720.38
NetR17_1: R17.1 R18.2 | length 45.2
  Top Layer w10: R18.2@2406.73,1118.57 2411.3,1114 R17.1@2450,1114
NetR24_2: R24.2 S1.2 | length 90
  Top Layer w10: R24.2@3325,535 S1.2@3325,625
NetR25_2: R25.2 S1.3 | length 90
  Top Layer w10: R25.2@3375,535 S1.3@3375,625
NetR26_2: R26.2 S1.4 | length 92
  Top Layer w10: R26.2@3425,533 S1.4@3425,625
NetR27_2: R27.2 S1.5 | length 95
  Top Layer w10: R27.2@3475,530 S1.5@3475,625
NetR28_2: R28.2 S1.6 | length 92
  Top Layer w10: R28.2@3525,533 S1.6@3525,625
NetR29_2: R29.2 S1.7 | length 90
  Top Layer w10: R29.2@3575,535 S1.7@3575,625
NetR30_2: R30.2 S1.8 | length 90
  Top Layer w10: R30.2@3625,535 S1.8@3625,625
NetR31_2: R31.2 S2.1 | length 90
  Top Layer w10: R31.2@3775,535 S2.1@3775,625
NetR32_2: R32.2 S2.2 | length 90
  Top Layer w10: R32.2@3825,535 S2.2@3825,625
NetR33_2: R33.2 S2.3 | length 90
  Top Layer w10: R33.2@3875,535 S2.3@3875,625
NetR34_2: R34.2 S2.4 | length 92
  Top Layer w10: R34.2@3925,533 S2.4@3925,625
NetR35_2: R35.2 S2.5 | length 95
  Top Layer w10: R35.2@3975,530 S2.5@3975,625
NetR36_2: R36.2 S2.6 | length 92
  Top Layer w10: R36.2@4025,533 S2.6@4025,625
NetR37_2: R37.2 S2.7 | length 90
  Top Layer w10: R37.2@4075,535 S2.7@4075,625
NetR38_2: R38.2 S2.8 | length 90
  Top Layer w10: R38.2@4125,535 S2.8@4125,625
NetR53_1: R53.1 R54.2 U2.2 | length 1384.9
  Signal Layer 2 w10: v3(2260.72,1016.91) 2260.9,1017.09 2262.01,1017.09 2313.12,1068.2 2544.04,1068.2 2819.77,792.47 2981.85,792.47 3073.02,701.3 v3(3115.69,701.3)
  Bottom Layer w10: R53.1@2255.15,1086.38 R54.2@2303.81,1086.38 ; v3(2260.72,1016.91) R53.1@2260.72,1081.92 ; R54.2@2306.85,1081.92 2313.5,1088.57 R54.2@2321,1088.57 ; v3(3115.69,701.3) 3116.27,700.71 3156.05,700.71 3161.91,706.57 3161.91,824.46 3125.49,860.88 U2.2@3125.49,868.76
NetR56_1: R56.1 U2.1 | length 83.3
  Bottom Layer w10: U2.1@3200.29,868.76 3283.26,868.76 R56.1@3283.5,869
R_FB: JP6.4 R46.2 | length 167.5
  Top Layer w10: R46.2@2998.63,1265.19 2998.63,1232.54 3045.12,1186.04 3111.48,1186.04 JP6.4@3113.44,1184.08
RT: R21.2 R49.1 U1.15 | length 152.6
  Top Layer w10: U1.15@2692.05,1266.83 2692.05,1208.47 2705.64,1194.87 2705.64,1173.64 R21.2@2705,1173 R49.1@2757.9,1173
SCL: J12.9 R22.1 R52.2 TP14.1 U1.9 | length 1924
  Top Layer w8: R22.1@2197.39,470 2200.67,466.72 J12.9@2200.67,298.77 ; v1(2552.02,1172.62) 2573.13,1193.73 2573.13,1266.02 U1.9@2573.94,1266.83
  Top Layer w10: R52.2@2132.32,470.12 2132.38,470.06 R22.1@2197.33,470.06 R22.1@2197.39,470
  Signal Layer 1 w10: TP14.1@2351.24,800 2200.67,649.42 J12.9@2200.67,298.77 2301.24,399.35 2301.24,558.39 2513.89,771.04 2513.89,1110.4 2552.02,1148.53 v1(2552.02,1172.62)
SDA: J12.10 R23.1 R51.2 TP15.1 U1.8 | length 1719.4
  Top Layer w8: J12.10@2200.67,198.77 2250.3,248.4 2250.3,398.35 2300.67,448.72 R23.1@2300.67,470 ; v1(2543.1,1204.01) 2543.1,1205.26 2554.25,1216.41 U1.8@2554.25,1266.83
  Top Layer w10: R23.1@2300.67,470 2300.86,470.19 2367.87,470.19 R51.2@2368.06,470.38
  Signal Layer 1 w10: J12.10@2200.67,198.77 2150.08,249.35 TP15.1@2150.08,800 2271.84,800 2472.81,1000.97 2472.81,1151.73 2523.56,1202.47 v1@2544.64,1202.47
SLOPE: R20.2 U1.14 | length 107.5
  Top Layer w10: R20.2@2650,1173 2657.5,1173 2662.5,1178 2662.5,1178.5 2672.36,1188.36 U1.14@2672.36,1266.83
SS/ATRK: C20.2 TP12.1 U1.16 | length 421.7
  Top Layer w10: U1.16@2711.73,1266.83 2712.64,1265.92 2712.64,1238.7 2712.64,1233.11 2749.87,1195.87 2780.73,1195.87 2781.04,1195.57 C20.2@2821.83,1195.57 C20.2@2820.83,1194.57
  Top Layer w20: v1(2820.83,1174.5) C20.2@2820.83,1194.57
  Signal Layer 1 w10: v1(2820.83,1174.5) 2849.98,1145.35 TP12.1@2849.98,945.21
SW1: C24.1 NT2.1 U1.36 | length 230.7
  Top Layer w10: 2425.94,1575.5 C24.1@2425.94,1580 ; 2443.21,1558 2455.59,1545.61 2455.83,1545.61 U1.36@2455.83,1495.17
  Top Layer w20: NT2.1@2329.97,1617.37 2352.85,1617.37 2353.1,1617.13 2414.23,1617.13 2425.94,1605.41 C24.1@2425.94,1589.5 ; 2425.94,1575.5 2443.21,1558 ; 2425.98,1575.46 C24.1@2425.98,1592
SW2: C23.2 C25.1 C39.1 D1.2 L1.2 Q3.5 Q4.1 Q4.2 Q4.3 TP7.1 U1.25 | length 461
  Top Layer w10: U1.25@2672.36,1495.17 2673.27,1496.08 2673.27,1528.89 2681.95,1537.57 2682.23,1537.57 2688.09,1543.43 2688.09,1568.55 2707.04,1587.5 C25.1@2707.04,1592
  Top Layer w20: C25.1@2707.04,1592 2733.08,1618.04 2804.36,1618.04 2827.13,1640.8 2827.13,1800.2 2797.32,1830 Q4.2@2789.57,1830
  other v1: 2690.08,1765.11 2750.08,1765.11 2660.08,1795.11 2780.08,1795.11 2717.21,1805.6 2690.08,1825.11 2750.08,1825.11 2810.08,1825.11 2660.08,1855.11 2720.08,1855.11 2780.08,1855.11 2660.08,1915.11 2720.08,1915.11 2780.08,1915.11 2690.08,1945.11 2750.08,1945.11 2810.08,1945.11 2660.08,1975.11 2720.08,1975.11 2780.08,1975.11 2690.08,2005.11 2750.08,2005.11 2810.08,2005.11 2720.08,2035.11 2780.08,2035.11 2720.08,2095.11 2780.08,2095.11 2690.08,2125.11 2750.08,2125.11 2810.08,2125.11 2660.08,2155.11 2690.08,2245.11 2750.08,2245.11 2810.08,2245.11 2660.08,2275.11 2720.08,2275.11 2780.08,2275.11 2840.08,2275.11 2630.08,2305.11 2690.08,2305.11 2750.08,2305.11 2810.08,2305.11 2660.08,2335.11 2720.08,2335.11 2780.08,2335.11 2840.08,2335.11 2630.08,2365.11 2690.08,2365.11 2750.08,2365.11 2810.08,2365.11 2660.08,2395.11 2838.08,2395.11 2630.08,2425.11 2810.08,2425.11 2660.08,2455.11 2838.08,2455.11 2630.08,2485.11 2810.08,2485.11 2660.08,2515.11 2838.08,2515.11 2630.08,2545.11 2810.08,2545.11 2660.08,2575.11 2838.08,2575.11 2630.08,2605.11 2690.08,2605.11 2750.08,2605.11 2810.08,2605.11 2660.08,2635.11 2720.08,2635.11 2780.08,2635.11 2838.08,2635.11 2630.08,2665.11 2690.08,2665.11 2750.08,2665.11 2810.08,2665.11 2747,2724 2824.6,2750.92 2664.89,2768.65 2658.72,2871.86 2823.15,2881.12
SYNC: C35.1 R48.2 TP11.1 U1.11 | length 548.1
  Top Layer w8: U1.11@2613.31,1266.83 2612.94,1266.46 2612.94,1228.39 2604.87,1220.32 2604.87,1160.84 2597.58,1153.54 2597.58,1052.08 2606.65,1043.01 2606.65,1042.91 2612.17,1037.39 2612.27,1037.39 2612.75,1036.91 R48.2@2620.15,1036.91 2627.65,1036.91 2650,1014.56 TP11.1@2650,800
  Top Layer w10: C35.1@2567.9,1037.39 R48.2@2612.17,1037.39
VBUS: J12.5 R22.2 R23.2 | length 407.3
  Top Layer w8: R22.2@2197.39,530 R23.2@2300.67,530
  Top Layer w10: R23.2@2300.67,530 2308.17,530 2343.55,494.62 2389.53,494.62 2400.67,483.48 J12.5@2400.67,298.77
VCC: C17.2 C42.1 D3.2 D4.2 J11.3 JP1.3 JP2.3 JP3.3 JP6.5 R16.1 R55.2 R58.1 TP10.1 U1.31 | length 6222.4
  Top Layer w10: TP10.1@2350.33,1015.33 2404.46,1015.33 2503.13,1114 R16.1@2513,1114 ; U1.31@2554.25,1495.17 2553.35,1496.08 2553.35,1544.87 2559.57,1551.09 C17.2@2559.57,1591.16 ; C17.2@2560,1602.51 v1@2560,1658
  Top Layer w20: D3.2@2538.31,1661.5 v1(2560,1661.5) D4.2@2585.69,1661.5
  Signal Layer 1 w10: J11.3@1400,200 1470,130 2900.04,130 ; JP3.3@2900.04,198.77 2900.04,130 ; JP2.3@3299.6,198.77 3299.6,130 ; JP1.3@3700,196.23 3633.77,130 3299.6,130 ; 2900.04,130 3299.6,130
  Signal Layer 2 w10: TP10.1@2350.33,1015.33 TP10.1@2350.33,1021.63 ; 2707.78,577.11 2708.89,576 3178.77,576 3190.38,587.61 v3(3196.87,587.61)
  Signal Layer 2 w15: TP10.1@2350.33,1015.33 2350.33,934.56 2707.78,577.11 ; 2708.89,576 2900.04,384.85 JP3.3@2900.04,198.77
  Bottom Layer w10: v3(3196.87,587.61) 3196.87,588.76 3256.87,648.76 R58.1@3256.87,656.26 C42.1@3295,656.26 3295,718.5 R55.2@3293.5,720
  Bottom Layer w15: TP10.1@2350.33,1021.63 2350.33,1450.33 v1@2560,1660 ; v1(2560,1661.5) 2648.49,1661.5 2813.1,1496.89 2813.1,1384.42 JP6.5@3113.44,1084.08
VEXT: J7.1 JP4.1 | length 1067
  Signal Layer 1 w10: JP4.1@150,900 76,826 76,691 567,200 J7.1@700,200
VIN: C1.1 C2.2 C3.2 C4.2 C5.1 C6.1 C31.1 J1.1 J5.1 J5.2 J5.3 JP4.3 JP5.3 Q1.5 R14.2 R40.2 R53.2 TP1.1 | length 5586.8
  Top Layer w10: JP5.3@1000,194.41 1000,209.28 1025,234.28 R14.2@1025,309.5
  Top Layer w20: v1(2259,1224.43) 2259.29,1224.71 2277,1224.71 R40.2@2277,1225
  Signal Layer 1 w8: J5.3@200,1950 210.9,1960.9 210.9,1981.28 232.76,2003.15 1911.42,2003.15 1925.49,1989.08 1925.49,1708.06 v1(1897.43,1680)
  Signal Layer 1 w10: J5.1@200,1750 200,850 JP4.3@150,800 200,750 200,632.88 555.94,276.94 917.47,276.94 JP5.3@1000,194.41
  Signal Layer 1 w20: TP1.1@1400,1600 1573.78,1426.22 1573.78,1248.53 1620,1202.32 2236.89,1202.32 v1(2259,1224.43)
  Bottom Layer w20: R53.2@2258.19,1144.91 2258.59,1145.32 2258.59,1224.02 v1(2259,1224.43)
  other v1: 1836.26,1241.73 1896.34,1241.73 1111.89,1264.49 267.59,1271.55 1866.34,1271.62 1926.34,1271.62 1629.14,1274.76 1753.06,1277.34 1836.26,1301.62 1896.34,1301.62 1956.34,1301.62 1464.86,1318.14 1306.43,1319.93 1700.13,1345.75 919.37,1353.11 1836.26,1361.51 1896.34,1361.51 1956.34,1361.51 1866.34,1391.4 1926.34,1391.4 1980,1391.04 2040.08,1391.04 1793.07,1397.38 1466.49,1410.29 1182.48,1412.74 1647.21,1433.53 1866.34,1451.29 1926.34,1451.29 1980,1450.93 2040.08,1450.93 2100.08,1450.93 2123.74,1480.46 1836.26,1481.29 1896.34,1481.29 1956.34,1481.29 2010.08,1480.82 2070.08,1480.82 115.11,1497.45 1734.98,1499.36 1330.73,1505.92 2123.74,1540.35 1836.26,1541.18 1889.92,1540.82 1949.92,1540.82 2010.08,1540.71 2070.08,1540.71 1554.27,1563.9 1919.92,1570.71 1980,1570.71 2040.08,1570.71 2100.08,1570.71 933.99,1584.98 1784,1600 1870.04,1616.93 1980,1630.71 2040.08,1630.71 2100.08,1630.71 1836.26,1637.37 1612.36,1659.42 1786.21,1667.8 1270.29,1672.33 1842,1680 1100,1697.86 1743.1,1712.35 1842,1740 1897.43,1740 349.48,1754.41 1591.7,1756.23 1423,1761 1801.3,1763.01 1866.34,1766.01 1842,1800 1897.43,1800 1698.84,1829.81 1784,1829.81 1506.95,1853.79 605.03,1854.65 1842,1860 1897.43,1860 1647.21,1881.44 1866.34,1890 1070,1910.41 1130,1910.41 1190,1910.41 1370,1910.41 719.51,1911.18 899.51,1911.18 959.51,1911.18 1019.51,1911.18 1784.04,1920.17 1842,1920 1897.43,1920 1567.18,1931.79 1100,1940.41 1160,1940.41 1340,1940.41 1400,1940.41 689.51,1941.18 749.51,1941.18 929.51,1941.18 989.51,1941.18 1714.33,1943.4 1489.73,1948.57 1629.14,1965 1070,1970.41 1130,1970.41 1190,1970.41 1250,1970.41 1310,1970.41 1370,1970.41 1842,1970.41 719.51,1971.18 779.51,1971.18 839.51,1971.18 899.51,1971.18 959.51,1971.18 1019.51,1971.18 1898.5,1970.97
VOUT: C14.2 C15.1 C32.1 J2.1 J6.1 J6.2 JP4.5 JP6.1 R6.2 R41.2 R43.2 R45.2 TP2.1 | length 8569.6
  Top Layer w10: R43.2@2860,1527 2861,1528 v1(2890,1528) 2892.68,1525.32 2892.68,1510.82 2923,1480.5 R41.2@2923,1473 R41.2@2923,1472 ; R41.2@2924,1473 R41.2@2923,1472 ; JP6.1@3103.44,1484.08 3069.89,1450.53 3002.51,1450.53 2997.63,1445.65 2942.85,1445.65 2923,1465.5 R41.2@2923,1472
  Signal Layer 1 w8: v1(2890,1528) 2891.86,1529.86 2906.08,1529.86 2921.86,1545.64 3040.62,1545.64 3061.52,1566.54 4093.31,1566.54 4171.52,1644.76 4171.52,1747.42 4186.29,1762.19 v1(4186.29,1785)
  Signal Layer 1 w10: JP4.5@150,700 153.11,696.89 153.11,654.49 556.68,250.91 734.32,250.91 754,231.24 754,144 789.29,108.71 4819.71,108.71 5300,589 J6.1@5300,1700
  other v1: 5141.56,1236.04 4699.22,1240.85 5402.75,1274.39 4803.96,1304.9 4657,1327 4497.54,1351.48 5255.57,1400.83 4370.27,1441.55 4603.27,1462.11 4464.25,1522.81 5223.98,1532.6 4584.92,1540.51 5397.33,1540.51 4360.52,1566.54 4257.68,1581.55 4665.93,1583.51 4299.29,1635.06 4587.27,1644.76 4208.61,1701.83 5183.02,1703.47 4328.05,1717.86 4413.94,1730.96 4473.94,1730.96 4533.94,1730.96 4593.94,1730.96 4653.94,1730.96 4713.94,1730.96 4253.6,1738.38 4823.56,1745.05 4383.94,1760.96 4443.94,1760.96 4503.94,1760.96 4563.94,1760.96 4623.94,1760.96 4683.94,1760.96 5075.16,1760.71 4318.57,1779.3 4413.94,1790.96 4473.94,1790.96 4653.94,1790.96 4713.94,1790.96 4907,1794.68 4383.94,1820.96 4443.94,1820.96 4623.94,1820.96 4683.94,1820.96 5162.3,1824.35 4218.68,1827.02 5420,1827 4287.1,1835.11 4345.2,1849.88 4413.94,1850.96 4473.94,1850.96 4653.94,1850.96 4713.94,1850.96 4383.94,1880.96 4443.94,1880.96 4623.94,1880.96 4683.94,1880.96 4793.21,1887.01 5043.1,1899.36 4191.13,1902.03 4413.94,1910.96 4473.94,1910.96 4653.94,1910.96 4713.94,1910.96 4235.18,1915.08 4295.18,1915.08
pads on no net: FID1.1 FID2.1 FID3.1 FID4.1 FID5.1 FID6.1 H1.1 H2.1 H3.1 H4.1 H5.0 H6.0 H7.0 H8.0 J12.1 J12.2 J12.3 J12.4 J12.7 J12.8 U1.2 U1.5 U1.21 U1.24 U1.28 U1.33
